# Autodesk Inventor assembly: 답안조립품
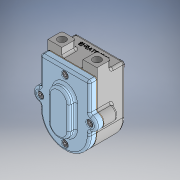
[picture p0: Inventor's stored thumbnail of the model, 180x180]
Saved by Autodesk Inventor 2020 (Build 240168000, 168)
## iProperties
Created: 2024-03
Part Number: 답안조립품
Document SubType Name: Assembly
Designer: 1강의실14
Author: 1강의실14
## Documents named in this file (9)
- C:\Users\1강의실14\Desktop\740304V1018\답안조립품.iam
- C:\Users\1강의실14\Desktop\740304V1018\본체.ipt
- C:\Users\1강의실14\Desktop\740304V1018\오일레스 부시.ipt
- C:\Users\1강의실14\Desktop\740304V1018\구동기어.ipt
- C:\Users\1강의실14\Desktop\740304V1018\오일 실 14 25 7.ipt
- C:\Users\1강의실14\Desktop\740304V1018\스퍼기어.ipt
- C:\Users\1강의실14\Desktop\740304V1018\가스켓.ipt
- C:\Users\1강의실14\Desktop\740304V1018\커버.ipt
- C:\Users\1강의실14\Desktop\740304V1018\육각 소켓 머리 볼트 M5x12.ipt
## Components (2 placed, 2 different names)
1. 구동기어:1
2. 가스켓:1
